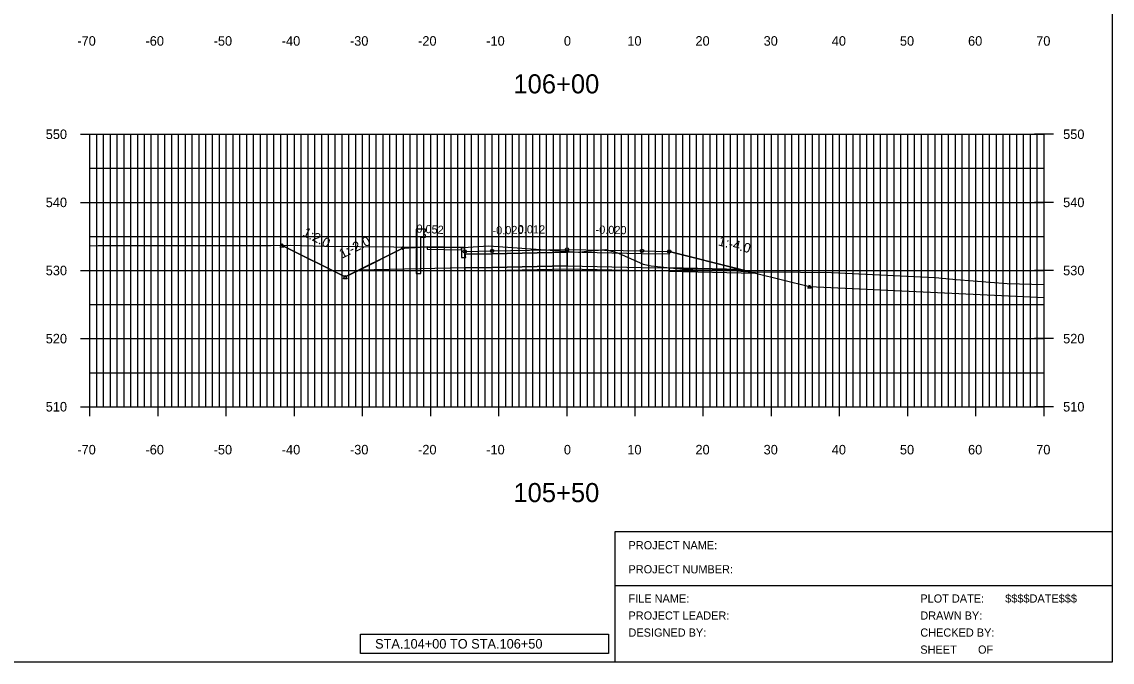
# Model space of a CAD drawing. Extents: x 1509063 to 1512863, y 401160 to 402918.
# Drawn here: x 1511982.7 to 1512142.7, y 402252.1 to 402346.1 of the extents above; entities that cross this region are included whole.
import ezdxf

# ---------------------------------------------------------------- set-up
doc = ezdxf.new("R2010")
doc.units = 0
for name, color, linetype in [('DD_P', 7, 'Continuous'), ('LCUT_P', 7, 'Continuous'), ('NBL1', 7, 'Continuous'), ('PET_P', 7, 'Continuous'), ('PRC', 7, 'Continuous'), ('PSP_P', 7, 'Continuous'), ('RBS_P', 7, 'Continuous'), ('RCC_P', 7, 'Continuous'), ('RGR_P', 7, 'Continuous'), ('XAX_P', 7, 'Continuous'), ('XAXTIC_P', 7, 'Continuous'), ('XAXTXT_P_T', 7, 'Continuous'), ('XFRAME_P', 7, 'Continuous'), ('XGL_P', 7, 'Continuous'), ('XSL1_P', 7, 'Continuous'), ('XSL1_P_T', 7, 'Continuous'), ('XSL2_P', 7, 'Continuous'), ('XSL3_P', 7, 'Continuous'), ('XSLOG', 7, 'Continuous')]:
    doc.layers.add(name, color=color, linetype=linetype)

msp = doc.modelspace()

# ---------------------------------------------------------------- linework, layer by layer
at = {"layer": 'DD_P'}
for points in [[(1512042.23, 402313.07), (1512038.65, 402312.85), (1512030.2, 402308.63), (1512020.91, 402313.27)], [(1512077.73, 402312.38), (1512090.41, 402309.21)]]:
    msp.add_lwpolyline(points, dxfattribs=at)
for points in [[(1512030.2, 402308.88), (1512030.45, 402308.38), (1512029.95, 402308.38)], [(1512098.32, 402307.48), (1512098.57, 402306.98), (1512098.07, 402306.98)]]:
    msp.add_lwpolyline(points, close=True, dxfattribs=at)
at = {"layer": 'LCUT_P'}
msp.add_lwpolyline([(1512020.91, 402313.52), (1512021.16, 402313.02), (1512020.66, 402313.02)], close=True, dxfattribs=at)
msp.add_lwpolyline([(1512090.41, 402309.21), (1512098.32, 402307.23), (1512132.73, 402305.62)], dxfattribs=at)
at = {"layer": 'NBL1'}
for p, q in [((1512069.81, 402271.25), (1512142.73, 402271.25)), ((1512069.81, 402252.08), (1512069.81, 402271.25)), ((1512069.81, 402263.33), (1512142.73, 402263.33))]:
    msp.add_line(p, q, dxfattribs=at)
msp.add_lwpolyline([(1512142.73, 402252.08), (1511822.73, 402252.08), (1511822.73, 402462.08), (1512142.73, 402462.08)], close=True, dxfattribs=at)
at = {"layer": 'PET_P'}
for centre in [(1512051.73, 402312.46), (1512073.73, 402312.46)]:
    msp.add_circle(centre, 0.25, dxfattribs=at)
at = {"layer": 'PRC'}
msp.add_circle((1512062.73, 402312.68), 0.25, dxfattribs=at)
at = {"layer": 'PSP_P'}
for centre in [(1512047.73, 402312.38), (1512077.73, 402312.38)]:
    msp.add_circle(centre, 0.25, dxfattribs=at)
at = {"layer": 'RBS_P'}
for points in [[(1512047.8, 402311.96), (1512051.73, 402312.04), (1512062.73, 402312.26), (1512062.73, 402310.26), (1512051.73, 402310.04), (1512047.8, 402309.96), (1512032.24, 402309.65), (1512038.65, 402312.85), (1512042.23, 402313.07), (1512042.23, 402312.73), (1512047.23, 402312.63), (1512047.23, 402311.47), (1512047.88, 402311.47)], [(1512062.73, 402312.26), (1512062.73, 402310.26), (1512073.73, 402310.04), (1512077.73, 402309.96), (1512088.24, 402309.75), (1512077.73, 402312.38), (1512077.73, 402311.96), (1512073.73, 402312.04)]]:
    msp.add_lwpolyline(points, close=True, dxfattribs=at)
for points in [[(1512038.65, 402312.85), (1512038.65, 402313.1), (1512038.65, 402312.85), (1512038.4, 402312.85), (1512038.65, 402312.85), (1512038.65, 402312.6), (1512038.65, 402312.85), (1512038.9, 402312.85)], [(1512077.73, 402312.38), (1512077.73, 402312.63), (1512077.73, 402312.38), (1512077.48, 402312.38), (1512077.73, 402312.38), (1512077.73, 402312.13), (1512077.73, 402312.38), (1512077.98, 402312.38)]]:
    msp.add_lwpolyline(points, dxfattribs=at)
at = {"layer": 'RCC_P'}
msp.add_lwpolyline([(1512047.73, 402312.38), (1512047.63, 402312.96), (1512047.23, 402312.97), (1512047.23, 402311.47), (1512047.88, 402311.47)], close=True, dxfattribs=at)
at = {"layer": 'RGR_P'}
msp.add_lwpolyline([(1512041.29, 402314.47), (1512041.98, 402314.47), (1512041.98, 402314.77), (1512041.68, 402315.05), (1512041.98, 402315.34), (1512041.98, 402315.64), (1512040.6, 402315.64), (1512040.6, 402309.14), (1512041.29, 402309.14)], close=True, dxfattribs=at)
at = {"layer": 'XAX_P'}
for p, q in [((1511992.73, 402289.58), (1511992.73, 402329.58)), ((1512062.73, 402289.58), (1512062.73, 402329.58)), ((1512132.73, 402289.58), (1512132.73, 402329.58)), ((1511992.73, 402289.58), (1512132.73, 402289.58))]:
    msp.add_line(p, q, dxfattribs=at)
at = {"layer": 'XAXTIC_P'}
for p, q in [((1511991.33, 402329.58), (1511994.13, 402329.58)), ((1512061.33, 402329.58), (1512064.13, 402329.58)), ((1512134.13, 402329.58), (1512131.33, 402329.58)), ((1511991.33, 402319.58), (1511994.13, 402319.58)), ((1512061.33, 402319.58), (1512064.13, 402319.58)), ((1512134.13, 402319.58), (1512131.33, 402319.58)), ((1511991.33, 402309.58), (1511994.13, 402309.58)), ((1512061.33, 402309.58), (1512064.13, 402309.58)), ((1512134.13, 402309.58), (1512131.33, 402309.58)), ((1511991.33, 402299.58), (1511994.13, 402299.58)), ((1512061.33, 402299.58), (1512064.13, 402299.58)), ((1512134.13, 402299.58), (1512131.33, 402299.58)), ((1511992.73, 402288.18), (1511992.73, 402290.98)), ((1512002.73, 402288.18), (1512002.73, 402290.98)), ((1512012.73, 402288.18), (1512012.73, 402290.98)), ((1512022.73, 402288.18), (1512022.73, 402290.98)), ((1512032.73, 402288.18), (1512032.73, 402290.98)), ((1512042.73, 402288.18), (1512042.73, 402290.98)), ((1512052.73, 402288.18), (1512052.73, 402290.98)), ((1512062.73, 402288.18), (1512062.73, 402290.98)), ((1512072.73, 402288.18), (1512072.73, 402290.98)), ((1512082.73, 402288.18), (1512082.73, 402290.98)), ((1512092.73, 402288.18), (1512092.73, 402290.98)), ((1512102.73, 402288.18), (1512102.73, 402290.98)), ((1512112.73, 402288.18), (1512112.73, 402290.98)), ((1512122.73, 402288.18), (1512122.73, 402290.98)), ((1512132.73, 402288.18), (1512132.73, 402290.98)), ((1511991.33, 402289.58), (1511994.13, 402289.58)), ((1512061.33, 402289.58), (1512064.13, 402289.58)), ((1512134.13, 402289.58), (1512131.33, 402289.58))]:
    msp.add_line(p, q, dxfattribs=at)
at = {"layer": 'XFRAME_P'}
msp.add_lwpolyline([(1512032.43, 402256.18), (1512068.83, 402256.18), (1512068.83, 402253.38), (1512032.43, 402253.38)], close=True, dxfattribs=at)
at = {"layer": 'XGL_P'}
for p, q in [((1511992.73, 402329.58), (1512132.73, 402329.58)), ((1511992.73, 402289.58), (1511992.73, 402329.58)), ((1511993.73, 402289.58), (1511993.73, 402329.58)), ((1511994.73, 402289.58), (1511994.73, 402329.58)), ((1511995.73, 402289.58), (1511995.73, 402329.58)), ((1511996.73, 402289.58), (1511996.73, 402329.58)), ((1511997.73, 402289.58), (1511997.73, 402329.58)), ((1511998.73, 402289.58), (1511998.73, 402329.58)), ((1511999.73, 402289.58), (1511999.73, 402329.58)), ((1512000.73, 402289.58), (1512000.73, 402329.58)), ((1512001.73, 402289.58), (1512001.73, 402329.58)), ((1512002.73, 402289.58), (1512002.73, 402329.58)), ((1512003.73, 402289.58), (1512003.73, 402329.58)), ((1512004.73, 402289.58), (1512004.73, 402329.58)), ((1512005.73, 402289.58), (1512005.73, 402329.58)), ((1512006.73, 402289.58), (1512006.73, 402329.58)), ((1512007.73, 402289.58), (1512007.73, 402329.58)), ((1512008.73, 402289.58), (1512008.73, 402329.58)), ((1512009.73, 402289.58), (1512009.73, 402329.58)), ((1512010.73, 402289.58), (1512010.73, 402329.58)), ((1512011.73, 402289.58), (1512011.73, 402329.58)), ((1512012.73, 402289.58), (1512012.73, 402329.58)), ((1512013.73, 402289.58), (1512013.73, 402329.58)), ((1512014.73, 402289.58), (1512014.73, 402329.58)), ((1512015.73, 402289.58), (1512015.73, 402329.58)), ((1512016.73, 402289.58), (1512016.73, 402329.58)), ((1512017.73, 402289.58), (1512017.73, 402329.58)), ((1512018.73, 402289.58), (1512018.73, 402329.58)), ((1512019.73, 402289.58), (1512019.73, 402329.58)), ((1512020.73, 402289.58), (1512020.73, 402329.58)), ((1512021.73, 402289.58), (1512021.73, 402329.58)), ((1512022.73, 402289.58), (1512022.73, 402329.58)), ((1512023.73, 402289.58), (1512023.73, 402329.58)), ((1512024.73, 402289.58), (1512024.73, 402329.58)), ((1512025.73, 402289.58), (1512025.73, 402329.58)), ((1512026.73, 402289.58), (1512026.73, 402329.58)), ((1512027.73, 402289.58), (1512027.73, 402329.58)), ((1512028.73, 402289.58), (1512028.73, 402329.58)), ((1512029.73, 402289.58), (1512029.73, 402329.58)), ((1512030.73, 402289.58), (1512030.73, 402329.58)), ((1512031.73, 402289.58), (1512031.73, 402329.58)), ((1512032.73, 402289.58), (1512032.73, 402329.58)), ((1512033.73, 402289.58), (1512033.73, 402329.58)), ((1512034.73, 402289.58), (1512034.73, 402329.58)), ((1512035.73, 402289.58), (1512035.73, 402329.58)), ((1512036.73, 402289.58), (1512036.73, 402329.58)), ((1512037.73, 402289.58), (1512037.73, 402329.58)), ((1512038.73, 402289.58), (1512038.73, 402329.58)), ((1512039.73, 402289.58), (1512039.73, 402329.58)), ((1512040.73, 402289.58), (1512040.73, 402329.58)), ((1512041.73, 402289.58), (1512041.73, 402329.58)), ((1512042.73, 402289.58), (1512042.73, 402329.58)), ((1512043.73, 402289.58), (1512043.73, 402329.58)), ((1512044.73, 402289.58), (1512044.73, 402329.58)), ((1512045.73, 402289.58), (1512045.73, 402329.58)), ((1512046.73, 402289.58), (1512046.73, 402329.58)), ((1512047.73, 402289.58), (1512047.73, 402329.58)), ((1512048.73, 402289.58), (1512048.73, 402329.58)), ((1512049.73, 402289.58), (1512049.73, 402329.58)), ((1512050.73, 402289.58), (1512050.73, 402329.58)), ((1512051.73, 402289.58), (1512051.73, 402329.58)), ((1512052.73, 402289.58), (1512052.73, 402329.58)), ((1512053.73, 402289.58), (1512053.73, 402329.58)), ((1512054.73, 402289.58), (1512054.73, 402329.58)), ((1512055.73, 402289.58), (1512055.73, 402329.58)), ((1512056.73, 402289.58), (1512056.73, 402329.58)), ((1512057.73, 402289.58), (1512057.73, 402329.58)), ((1512058.73, 402289.58), (1512058.73, 402329.58)), ((1512059.73, 402289.58), (1512059.73, 402329.58)), ((1512060.73, 402289.58), (1512060.73, 402329.58)), ((1512061.73, 402289.58), (1512061.73, 402329.58)), ((1512062.73, 402289.58), (1512062.73, 402329.58)), ((1512063.73, 402289.58), (1512063.73, 402329.58)), ((1512064.73, 402289.58), (1512064.73, 402329.58)), ((1512065.73, 402289.58), (1512065.73, 402329.58)), ((1512066.73, 402289.58), (1512066.73, 402329.58)), ((1512067.73, 402289.58), (1512067.73, 402329.58)), ((1512068.73, 402289.58), (1512068.73, 402329.58)), ((1512069.73, 402289.58), (1512069.73, 402329.58)), ((1512070.73, 402289.58), (1512070.73, 402329.58)), ((1512071.73, 402289.58), (1512071.73, 402329.58)), ((1512072.73, 402289.58), (1512072.73, 402329.58)), ((1512073.73, 402289.58), (1512073.73, 402329.58)), ((1512074.73, 402289.58), (1512074.73, 402329.58)), ((1512075.73, 402289.58), (1512075.73, 402329.58)), ((1512076.73, 402289.58), (1512076.73, 402329.58)), ((1512077.73, 402289.58), (1512077.73, 402329.58)), ((1512078.73, 402289.58), (1512078.73, 402329.58)), ((1512079.73, 402289.58), (1512079.73, 402329.58)), ((1512080.73, 402289.58), (1512080.73, 402329.58)), ((1512081.73, 402289.58), (1512081.73, 402329.58)), ((1512082.73, 402289.58), (1512082.73, 402329.58)), ((1512083.73, 402289.58), (1512083.73, 402329.58)), ((1512084.73, 402289.58), (1512084.73, 402329.58)), ((1512085.73, 402289.58), (1512085.73, 402329.58)), ((1512086.73, 402289.58), (1512086.73, 402329.58)), ((1512087.73, 402289.58), (1512087.73, 402329.58)), ((1512088.73, 402289.58), (1512088.73, 402329.58)), ((1512089.73, 402289.58), (1512089.73, 402329.58)), ((1512090.73, 402289.58), (1512090.73, 402329.58)), ((1512091.73, 402289.58), (1512091.73, 402329.58)), ((1512092.73, 402289.58), (1512092.73, 402329.58)), ((1512093.73, 402289.58), (1512093.73, 402329.58)), ((1512094.73, 402289.58), (1512094.73, 402329.58)), ((1512095.73, 402289.58), (1512095.73, 402329.58)), ((1512096.73, 402289.58), (1512096.73, 402329.58)), ((1512097.73, 402289.58), (1512097.73, 402329.58)), ((1512098.73, 402289.58), (1512098.73, 402329.58)), ((1512099.73, 402289.58), (1512099.73, 402329.58)), ((1512100.73, 402289.58), (1512100.73, 402329.58)), ((1512101.73, 402289.58), (1512101.73, 402329.58)), ((1512102.73, 402289.58), (1512102.73, 402329.58)), ((1512103.73, 402289.58), (1512103.73, 402329.58)), ((1512104.73, 402289.58), (1512104.73, 402329.58)), ((1512105.73, 402289.58), (1512105.73, 402329.58)), ((1512106.73, 402289.58), (1512106.73, 402329.58)), ((1512107.73, 402289.58), (1512107.73, 402329.58)), ((1512108.73, 402289.58), (1512108.73, 402329.58)), ((1512109.73, 402289.58), (1512109.73, 402329.58)), ((1512110.73, 402289.58), (1512110.73, 402329.58)), ((1512111.73, 402289.58), (1512111.73, 402329.58)), ((1512112.73, 402289.58), (1512112.73, 402329.58)), ((1512113.73, 402289.58), (1512113.73, 402329.58)), ((1512114.73, 402289.58), (1512114.73, 402329.58)), ((1512115.73, 402289.58), (1512115.73, 402329.58)), ((1512116.73, 402289.58), (1512116.73, 402329.58)), ((1512117.73, 402289.58), (1512117.73, 402329.58)), ((1512118.73, 402289.58), (1512118.73, 402329.58)), ((1512119.73, 402289.58), (1512119.73, 402329.58)), ((1512120.73, 402289.58), (1512120.73, 402329.58)), ((1512121.73, 402289.58), (1512121.73, 402329.58)), ((1512122.73, 402289.58), (1512122.73, 402329.58)), ((1512123.73, 402289.58), (1512123.73, 402329.58)), ((1512124.73, 402289.58), (1512124.73, 402329.58)), ((1512125.73, 402289.58), (1512125.73, 402329.58)), ((1512126.73, 402289.58), (1512126.73, 402329.58)), ((1512127.73, 402289.58), (1512127.73, 402329.58)), ((1512128.73, 402289.58), (1512128.73, 402329.58)), ((1512129.73, 402289.58), (1512129.73, 402329.58)), ((1512130.73, 402289.58), (1512130.73, 402329.58)), ((1512131.73, 402289.58), (1512131.73, 402329.58)), ((1512132.73, 402289.58), (1512132.73, 402329.58)), ((1511992.73, 402324.58), (1512132.73, 402324.58)), ((1511992.73, 402319.58), (1512132.73, 402319.58)), ((1511992.73, 402314.58), (1512132.73, 402314.58)), ((1511992.73, 402309.58), (1512132.73, 402309.58)), ((1511992.73, 402304.58), (1512132.73, 402304.58)), ((1511992.73, 402299.58), (1512132.73, 402299.58)), ((1511992.73, 402294.58), (1512132.73, 402294.58)), ((1511992.73, 402289.58), (1512132.73, 402289.58))]:
    msp.add_line(p, q, dxfattribs=at)
at = {"layer": 'XSL1_P'}
msp.add_lwpolyline([(1512020.91, 402313.27), (1512030.2, 402308.63), (1512032.24, 402309.65), (1512038.65, 402312.85), (1512042.23, 402313.07), (1512047.23, 402312.97), (1512047.63, 402312.96), (1512047.73, 402312.38), (1512051.73, 402312.46), (1512062.73, 402312.68), (1512073.73, 402312.46), (1512077.73, 402312.38), (1512088.24, 402309.75), (1512090.41, 402309.21), (1512098.32, 402307.23)], dxfattribs=at)
msp.add_lwpolyline([(1512047.23, 402312.97), (1512042.23, 402313.07), (1512042.23, 402312.73), (1512047.23, 402312.63)], close=True, dxfattribs=at)
at = {"layer": 'XSL2_P'}
for points in [[(1512047.8, 402309.96), (1512032.24, 402309.65)], [(1512088.24, 402309.75), (1512077.73, 402309.96)]]:
    msp.add_lwpolyline(points, dxfattribs=at)
for points in [[(1512073.73, 402309.54), (1512062.73, 402309.76), (1512051.73, 402309.54), (1512047.8, 402309.46), (1512047.8, 402309.96), (1512051.73, 402310.04), (1512062.73, 402310.26), (1512073.73, 402310.04), (1512077.73, 402309.96), (1512077.73, 402309.46)], [(1512077.73, 402309.96), (1512077.73, 402309.46), (1512090.41, 402309.21), (1512088.24, 402309.75)]]:
    msp.add_lwpolyline(points, close=True, dxfattribs=at)
at = {"layer": 'XSL3_P'}
msp.add_lwpolyline([(1512051.73, 402312.04), (1512047.8, 402311.96), (1512047.73, 402312.38), (1512051.73, 402312.46), (1512062.73, 402312.68), (1512073.73, 402312.46), (1512077.73, 402312.38), (1512077.73, 402311.96), (1512073.73, 402312.04), (1512062.73, 402312.26)], close=True, dxfattribs=at)
at = {"layer": 'XSLOG'}
msp.add_lwpolyline([(1511992.73, 402313.22), (1511993.94, 402313.23), (1512019.31, 402313.25), (1512022.12, 402313.29), (1512027.2, 402313.17), (1512047.42, 402312.97), (1512051.26, 402313.18), (1512064.4, 402312.27), (1512064.54, 402312.28), (1512065.26, 402312.35), (1512068.42, 402312.67), (1512070.27, 402312.14), (1512073.89, 402310.49), (1512075.08, 402310.26), (1512079.74, 402309.77), (1512081.19, 402309.71), (1512082.6, 402309.64), (1512086.69, 402309.63), (1512089.32, 402309.38), (1512096.97, 402309.32), (1512101.52, 402309.29), (1512108.56, 402308.96), (1512113.63, 402308.72), (1512114.62, 402308.65), (1512116.81, 402308.54), (1512117.3, 402308.5), (1512119.85, 402308.28), (1512127.34, 402307.65), (1512132.73, 402307.53)], dxfattribs=at)

# ---------------------------------------------------------------- texts
at = {"layer": 'NBL1'}
for s, p in [('PROJECT NAME:', (1512071.75, 402268.65)), ('PROJECT NUMBER:', (1512071.75, 402265.12)), ('FILE NAME:', (1512071.75, 402260.83)), ('PLOT DATE:', (1512114.57, 402260.83)), ('$$$$DATE$$$', (1512127.03, 402260.83)), ('PROJECT LEADER:', (1512071.75, 402258.33)), ('DRAWN BY:', (1512114.57, 402258.33)), ('DESIGNED BY:', (1512071.75, 402255.83)), ('CHECKED BY:', (1512114.57, 402255.83)), ('SHEET       OF', (1512114.57, 402253.33))]:
    msp.add_text(s, height=1.2, rotation=360, dxfattribs=at).set_placement(p)
at = {"layer": 'XAXTXT_P_T'}
for s, height, p in [('-70', 1.4, (1511990.88, 402342.58)), ('-60', 1.4, (1512000.88, 402342.58)), ('-50', 1.4, (1512010.88, 402342.58)), ('-40', 1.4, (1512020.88, 402342.58)), ('-30', 1.4, (1512030.88, 402342.58)), ('-20', 1.4, (1512040.88, 402342.58)), ('-10', 1.4, (1512050.88, 402342.58)), ('0', 1.4, (1512062.27, 402342.58)), ('10', 1.4, (1512071.58, 402342.58)), ('20', 1.4, (1512081.58, 402342.58)), ('30', 1.4, (1512091.58, 402342.58)), ('40', 1.4, (1512101.58, 402342.58)), ('50', 1.4, (1512111.58, 402342.58)), ('60', 1.4, (1512121.58, 402342.58)), ('70', 1.4, (1512131.58, 402342.58)), ('106+00', 2.8, (1512054.87, 402335.58)), ('550', 1.4, (1511986.24, 402328.88)), ('550', 1.4, (1512135.53, 402328.88)), ('540', 1.4, (1511986.24, 402318.88)), ('540', 1.4, (1512135.53, 402318.88)), ('530', 1.4, (1511986.24, 402308.88)), ('530', 1.4, (1512135.53, 402308.88)), ('520', 1.4, (1511986.24, 402298.88)), ('520', 1.4, (1512135.53, 402298.88)), ('510', 1.4, (1511986.24, 402288.88)), ('510', 1.4, (1512135.53, 402288.88)), ('-70', 1.4, (1511990.88, 402282.58)), ('-60', 1.4, (1512000.88, 402282.58)), ('-50', 1.4, (1512010.88, 402282.58)), ('-40', 1.4, (1512020.88, 402282.58)), ('-30', 1.4, (1512030.88, 402282.58)), ('-20', 1.4, (1512040.88, 402282.58)), ('-10', 1.4, (1512050.88, 402282.58)), ('0', 1.4, (1512062.27, 402282.58)), ('10', 1.4, (1512071.58, 402282.58)), ('20', 1.4, (1512081.58, 402282.58)), ('30', 1.4, (1512091.58, 402282.58)), ('40', 1.4, (1512101.58, 402282.58)), ('50', 1.4, (1512111.58, 402282.58)), ('60', 1.4, (1512121.58, 402282.58)), ('70', 1.4, (1512131.58, 402282.58)), ('105+50', 2.8, (1512054.87, 402275.58))]:
    msp.add_text(s, height=height, dxfattribs=at).set_placement(p)
at = {"layer": 'XFRAME_P'}
msp.add_text('STA.104+00 TO STA.106+50', height=1.4, dxfattribs=at).set_placement((1512034.57, 402254.08))
at = {"layer": 'XSL1_P_T'}
for s, height, rotation, p in [('1:2.0', 1.4, 333.4349, (1512023.82, 402314.72)), ('1:2.0', 1.4, 333.4349, (1512023.82, 402314.72)), ('1:2.0', 1.4, 333.4349, (1512023.82, 402314.72)), ('0.052', 1.2, 356.9978, (1512040.6, 402315.15)), ('-0.020', 1.2, 1.1458, (1512051.81, 402314.86)), ('0.012', 1.2, 359.3017, (1512055.5, 402315.05)), ('0.012', 1.2, 359.3017, (1512055.5, 402315.05)), ('-0.020', 1.2, 358.8542, (1512066.91, 402314.99)), ('1:-2.0', 1.4, 26.5651, (1512029.74, 402311.31)), ('1:-2.0', 1.4, 26.5651, (1512029.74, 402311.31)), ('1:-2.0', 1.4, 26.5651, (1512029.74, 402311.31)), ('1:-4.0', 1.4, 345.9638, (1512084.84, 402313.28)), ('1:-4.0', 1.4, 345.9638, (1512084.84, 402313.28)), ('1:-4.0', 1.4, 345.9638, (1512084.84, 402313.28))]:
    msp.add_text(s, height=height, rotation=rotation, dxfattribs=at).set_placement(p)

doc.saveas('drawing.dxf')
